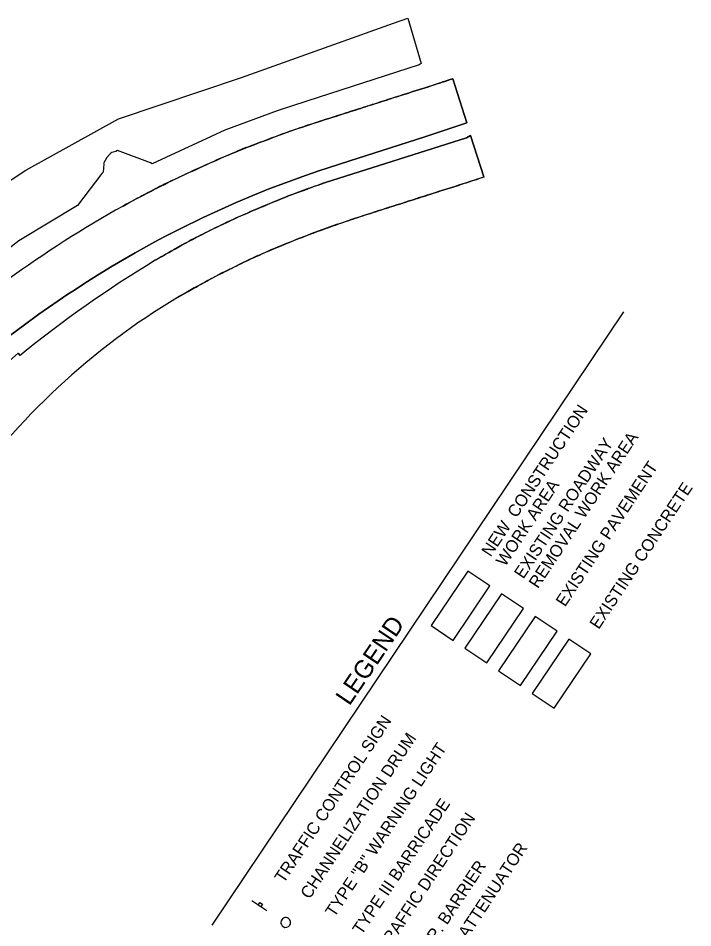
# Model space of a CAD drawing. Extents: x 1795987 to 1799700, y 243690 to 251545.
# Drawn here: x 1798427 to 1798861, y 250393 to 250979 of the extents above; entities that cross this region are included whole.
import ezdxf

# ---------------------------------------------------------------- set-up
doc = ezdxf.new("R2010")
doc.units = 0
for name, color, linetype in [('6', 7, 'Continuous'), ('EP', 7, 'Continuous'), ('Level 15', 7, 'Continuous'), ('Level 31', 7, 'Continuous'), ('Prop_Horiz Alignment', 7, 'Continuous')]:
    doc.layers.add(name, color=color, linetype=linetype)

msp = doc.modelspace()

# ---------------------------------------------------------------- linework, layer by layer
at = {"layer": '6'}
msp.add_line((1798494.24, 250858.44), (1798494.24, 250858.44), dxfattribs=at)
at = {"layer": 'EP'}
for points in [[(1798706.75, 250940.4), (1798715.83, 250911.99), (1798688.08, 250902.78)], [(1798688.08, 250902.78), (1798640.4, 250887.61), (1798619.79, 250880.85), (1798609.55, 250877.31), (1798594.28, 250871.72), (1798588.83, 250869.62), (1798577.96, 250865.27), (1798567.18, 250860.72), (1798560.03, 250857.58), (1798545.85, 250851.06), (1798531.03, 250843.81), (1798521.26, 250838.77), (1798514.78, 250835.33), (1798501.95, 250828.23), (1798487.33, 250819.69), (1798477.69, 250813.81), (1798471.32, 250809.8), (1798461.79, 250803.59)], [(1798461.79, 250803.59), (1798458.71, 250801.58), (1798446.15, 250793.04), (1798439.94, 250788.67), (1798430.71, 250781.98), (1798421.6, 250775.14)]]:
    msp.add_lwpolyline(points, dxfattribs=at)
msp.add_ellipse((1798858.33, 250206.09), major_axis=(-551.38, -506.31), ratio=0.997868, start_param=4.47912, end_param=4.715266, dxfattribs=at)
msp.add_spline([(1798494.24, 250858.44), (1798511.92, 250867.84), (1798529.89, 250876.75), (1798548.16, 250885.14), (1798566.63, 250893.22), (1798586, 250900.7), (1798605.06, 250907.69), (1798624.48, 250914.08), (1798644, 250920.28), (1798656.95, 250924.45), (1798676, 250930.54), (1798693.15, 250936.02), (1798706.75, 250940.4)], degree=3, dxfattribs=at)
at = {"layer": 'Level 15'}
for p, q in [((1798718.26, 250903.94), (1798726.68, 250877.25)), ((1798624.79, 250873.67), (1798715.6, 250902.36)), ((1798726.68, 250877.25), (1798727, 250877.2)), ((1798426.65, 250763.71), (1798427.89, 250762.21))]:
    msp.add_line(p, q, dxfattribs=at)
msp.add_lwpolyline([(1798715.6, 250902.36), (1798718.26, 250903.94)], dxfattribs=at)
for centre, radius, start, end in [((1798929.58, 250141.63), 798, 121.30087, 128.95287), ((1798765.83, 250404.81), 460.1, 120.94106, 144.97812), ((1798847.3, 250280.46), 640.68, 131.03833, 159.15988)]:
    msp.add_arc(centre, radius, start, end, dxfattribs=at)
for points in [[(1798727, 250877.2), (1798714.67, 250873.14), (1798697.52, 250867.68), (1798678.08, 250861.49), (1798658.57, 250855.27), (1798639.15, 250848.9), (1798619.93, 250842.16), (1798601.24, 250834.92), (1798582.64, 250827.07), (1798564.5, 250818.45), (1798546.7, 250809.25), (1798529.27, 250799.44)], [(1798514.99, 250823.48), (1798532.39, 250833.36), (1798550.16, 250842.6), (1798568.32, 250851.19), (1798586.83, 250859.19), (1798605.69, 250866.74), (1798624.79, 250873.67)]]:
    msp.add_spline(points, degree=3, dxfattribs=at)
at = {"layer": 'Level 31'}
for p, q in [((1798551.69, 250395.05), (1798817.07, 250790.3)), ((1798587.01, 250404.22), (1798577.3, 250410.74))]:
    msp.add_line(p, q, dxfattribs=at)
for points in [[(1798706.99, 250578.57), (1798730.56, 250613.67), (1798716.38, 250623.19), (1798692.82, 250588.09)], [(1798728.71, 250563.99), (1798752.28, 250599.09), (1798738.11, 250608.6), (1798714.54, 250573.51)], [(1798750.44, 250549.41), (1798774, 250584.5), (1798759.83, 250594.02), (1798736.26, 250558.92)], [(1798772.16, 250534.82), (1798795.72, 250569.92), (1798781.55, 250579.43), (1798757.99, 250544.34)], [(1798581.34, 250408.03), (1798582.43, 250409.65), (1798584.05, 250408.56), (1798582.96, 250406.94)]]:
    msp.add_lwpolyline(points, close=True, dxfattribs=at)
for start, end in [(56.12215, 236.12215), (236.12215, 56.12215)]:
    msp.add_arc((1798599.13, 250396.78), 3.18, start, end, dxfattribs=at)
at = {"layer": 'Prop_Horiz Alignment'}
for p, q in [((1798630, 250962.47), (1798668.45, 250976.22)), ((1798630, 250962.47), (1798668.45, 250976.22)), ((1798668.45, 250976.22), (1798677.83, 250979.45)), ((1798668.45, 250976.22), (1798677.83, 250979.45)), ((1798677.83, 250979.45), (1798686.34, 250950.23)), ((1798677.83, 250979.45), (1798686.34, 250950.23)), ((1798570.52, 250941.2), (1798630, 250962.47)), ((1798570.52, 250941.2), (1798630, 250962.47)), ((1798491.32, 250914.63), (1798570.52, 250941.2)), ((1798491.32, 250914.63), (1798570.52, 250941.2)), ((1798612.69, 250926), (1798593.64, 250919.71)), ((1798612.69, 250926), (1798593.64, 250919.71)), ((1798593.64, 250919.71), (1798559.85, 250907.31)), ((1798593.64, 250919.71), (1798559.85, 250907.31)), ((1798431.57, 250881.49), (1798491.32, 250914.63)), ((1798431.57, 250881.49), (1798491.32, 250914.63)), ((1798559.85, 250907.31), (1798513, 250885.53)), ((1798559.85, 250907.31), (1798513, 250885.53)), ((1798489.61, 250893.48), (1798487.03, 250892.83)), ((1798489.61, 250893.48), (1798487.03, 250892.83)), ((1798490.6, 250894.25), (1798489.61, 250893.48)), ((1798490.6, 250894.25), (1798489.61, 250893.48)), ((1798512, 250886.32), (1798490.6, 250894.25)), ((1798512, 250886.32), (1798490.6, 250894.25)), ((1798513, 250885.53), (1798512, 250886.32)), ((1798513, 250885.53), (1798512, 250886.32)), ((1798399.82, 250860.78), (1798431.57, 250881.49)), ((1798399.82, 250860.78), (1798431.57, 250881.49)), ((1798481.52, 250880.29), (1798480.51, 250879.39)), ((1798481.52, 250880.29), (1798480.51, 250879.39)), ((1798480.51, 250879.39), (1798464.83, 250858.78)), ((1798480.51, 250879.39), (1798464.83, 250858.78)), ((1798464.83, 250858.78), (1798427.17, 250835.94)), ((1798464.83, 250858.78), (1798427.17, 250835.94)), ((1798427.17, 250835.94), (1798396.98, 250812.82)), ((1798427.17, 250835.94), (1798396.98, 250812.82))]:
    msp.add_line(p, q, dxfattribs=at)
for points in [[(1798686.34, 250950.23), (1798685.01, 250949.46), (1798612.69, 250926)], [(1798686.34, 250950.23), (1798685.01, 250949.46), (1798612.69, 250926)], [(1798421.6, 250775.14), (1798430.71, 250781.98), (1798439.94, 250788.67), (1798446.15, 250793.04), (1798458.71, 250801.58), (1798461.79, 250803.59), (1798471.32, 250809.8), (1798477.69, 250813.81), (1798487.33, 250819.69), (1798501.95, 250828.23), (1798514.78, 250835.33), (1798521.26, 250838.77), (1798531.03, 250843.81), (1798545.85, 250851.06), (1798560.03, 250857.58), (1798567.18, 250860.72), (1798577.96, 250865.27), (1798588.83, 250869.62), (1798594.28, 250871.72), (1798609.55, 250877.31), (1798619.79, 250880.85), (1798640.4, 250887.61), (1798688.08, 250902.78), (1798715.83, 250911.99), (1798706.75, 250940.4)], [(1798727, 250877.2), (1798726.68, 250877.25), (1798718.26, 250903.94), (1798715.6, 250902.36), (1798624.79, 250873.67)], [(1798487.03, 250892.83), (1798486.29, 250892.47), (1798485.52, 250891.59)], [(1798487.03, 250892.83), (1798486.29, 250892.47), (1798485.52, 250891.59)], [(1798485.52, 250891.59), (1798483.88, 250889.72), (1798481.58, 250885.86)], [(1798485.52, 250891.59), (1798483.88, 250889.72), (1798481.58, 250885.86)], [(1798481.58, 250885.86), (1798481.89, 250885.49), (1798481.52, 250880.29)], [(1798481.58, 250885.86), (1798481.89, 250885.49), (1798481.52, 250880.29)], [(1798494.24, 250858.44), (1798494.24, 250858.44)], [(1798427.89, 250762.21), (1798426.65, 250763.71)], [(1798736.26, 250558.92), (1798750.44, 250549.41), (1798774, 250584.5), (1798759.83, 250594.02), (1798736.26, 250558.92)]]:
    msp.add_lwpolyline(points, dxfattribs=at)
for centre, radius, start, end in [((1798929.58, 250141.63), 798, 121.30087, 128.95287), ((1798765.83, 250404.81), 460.1, 120.94106, 144.97812), ((1798847.3, 250280.46), 640.68, 131.03833, 159.15988)]:
    msp.add_arc(centre, radius, start, end, dxfattribs=at)
msp.add_ellipse((1798858.33, 250206.09), major_axis=(-551.38, -506.31), ratio=0.997868, start_param=4.47912, end_param=4.715266, dxfattribs=at)
for points in [[(1798706.75, 250940.4), (1798702.22, 250938.94), (1798697.68, 250937.48), (1798693.15, 250936.02), (1798687.44, 250934.18), (1798681.72, 250932.37), (1798676, 250930.54), (1798669.65, 250928.51), (1798663.3, 250926.48), (1798656.95, 250924.45), (1798652.63, 250923.07), (1798648.31, 250921.67), (1798644, 250920.28), (1798637.5, 250918.2), (1798630.98, 250916.15), (1798624.48, 250914.08), (1798617.99, 250912.01), (1798611.51, 250909.9), (1798605.06, 250907.69), (1798598.66, 250905.49), (1798592.34, 250903.08), (1798586, 250900.7), (1798579.52, 250898.27), (1798573.03, 250895.85), (1798566.63, 250893.22), (1798560.41, 250890.67), (1798554.29, 250887.9), (1798548.16, 250885.14), (1798542.05, 250882.39), (1798535.95, 250879.62), (1798529.89, 250876.75), (1798523.84, 250873.89), (1798517.82, 250870.99), (1798511.92, 250867.84), (1798506.03, 250864.71), (1798500.13, 250861.57), (1798494.24, 250858.44)], [(1798529.27, 250799.44), (1798535.08, 250802.71), (1798540.89, 250805.98), (1798546.7, 250809.25), (1798552.52, 250812.53), (1798558.52, 250815.47), (1798564.5, 250818.45), (1798570.5, 250821.44), (1798576.52, 250824.34), (1798582.64, 250827.07), (1798588.79, 250829.82), (1798594.99, 250832.41), (1798601.24, 250834.92), (1798607.44, 250837.42), (1798613.65, 250839.87), (1798619.93, 250842.16), (1798626.31, 250844.49), (1798632.7, 250846.76), (1798639.15, 250848.9), (1798645.61, 250851.05), (1798652.08, 250853.2), (1798658.57, 250855.27), (1798665.07, 250857.34), (1798671.58, 250859.42), (1798678.08, 250861.49), (1798684.56, 250863.55), (1798691.04, 250865.61), (1798697.52, 250867.68), (1798703.23, 250869.5), (1798708.97, 250871.26), (1798714.67, 250873.14), (1798718.78, 250874.49), (1798722.89, 250875.85), (1798727, 250877.2)], [(1798624.79, 250873.67), (1798618.42, 250871.36), (1798612.05, 250869.05), (1798605.69, 250866.74), (1798599.32, 250864.43), (1798593.08, 250861.79), (1798586.83, 250859.19), (1798580.62, 250856.61), (1798574.46, 250853.94), (1798568.32, 250851.19), (1798562.21, 250848.44), (1798556.17, 250845.57), (1798550.16, 250842.6), (1798544.17, 250839.64), (1798538.2, 250836.66), (1798532.39, 250833.36), (1798526.59, 250830.07), (1798520.79, 250826.78), (1798514.99, 250823.48)]]:
    msp.add_open_spline(points, degree=3, dxfattribs=at)

# ---------------------------------------------------------------- texts
at = {"layer": 'Level 31'}
for s, height, rotation, p in [('NEW  CONSTRUCTION', 7.7999, 56.43516, (1798731.16, 250631.88)), ('REMOVAL WORK AREA', 7.7999, 56.43516, (1798761.62, 250611.5)), ('EXISTING ROADWAY', 7.7999, 56.43516, (1798752.25, 250617.72)), ('EXISTING PAVEMENT', 7.7999, 56.43516, (1798779.07, 250599.73)), ('WORK AREA', 7.8, 56.43516, (1798740.52, 250625.66)), ('EXISTING CONCRETE', 7.7999, 56.43516, (1798800.83, 250585.21)), ('LEGEND', 11.7, 55.95613, (1798640.14, 250535.91)), ('TRAFFIC CONTROL SIGN', 7.7999, 56.43516, (1798597.78, 250421.64)), ('CHANNELIZATION DRUM', 7.7999, 56.43516, (1798614.45, 250411.34)), ('TYPE "B" WARNING LIGHT', 7.7999, 56.43516, (1798630.52, 250399.65)), ('TYPE III BARRICADE', 7.7999, 55.95613, (1798648, 250388.28)), ('TRAFFIC DIRECTION', 7.7999, 56.43516, (1798664.08, 250377.29)), ('TEMP. ATTENUATOR', 7.7999, 56.43516, (1798696.96, 250357.06)), ('TEMP. BARRIER', 7.7999, 56.43516, (1798683.78, 250365.84))]:
    msp.add_text(s, height=height, rotation=rotation, dxfattribs=at).set_placement(p)

doc.saveas('drawing.dxf')
